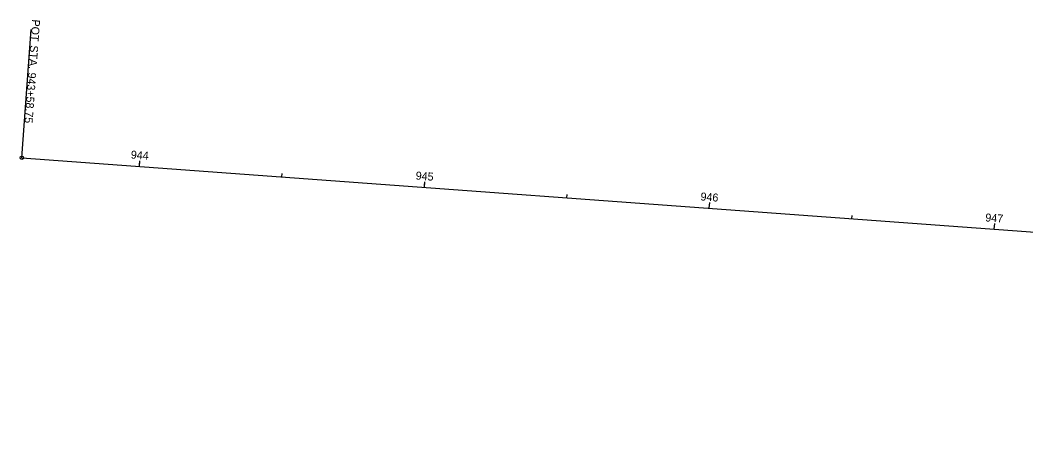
# Model space of a CAD drawing. Extents: x 1981066 to 1984208, y 708139 to 709503.
# Drawn here: x 1981065.5 to 1981417.5, y 708968.6 to 709112.1 of the extents above; entities that cross this region are included whole.
import ezdxf

# ---------------------------------------------------------------- set-up
doc = ezdxf.new("R2010")
doc.units = 0
for name, color, linetype in [('PM_X_Edge_Line', 7, 'Continuous'), ('PV_P_EOP', 7, 'Continuous'), ('PV_X_EOP', 7, 'Continuous'), ('RD_X_Wall', 7, 'Continuous'), ('SV_P_Mon_Cells_Set', 7, 'Continuous'), ('SV_X_Break_Lines', 7, 'Continuous'), ('TopoDOT Temp', 7, 'Continuous')]:
    doc.layers.add(name, color=color, linetype=linetype)

msp = doc.modelspace()

# ---------------------------------------------------------------- linework, layer by layer
at = {"layer": 'PM_X_Edge_Line'}
for p, q in [((1981107.26, 709060.84), (1981107.41, 709062.83)), ((1981157.12, 709057.17), (1981157.21, 709058.36)), ((1981206.99, 709053.5), (1981207.14, 709055.49)), ((1981256.85, 709049.83), (1981256.94, 709051.02)), ((1981306.72, 709046.16), (1981306.87, 709048.15)), ((1981356.59, 709042.49), (1981356.67, 709043.68)), ((1981406.45, 709038.82), (1981406.6, 709040.81))]:
    msp.add_line(p, q, dxfattribs=at)
at = {"layer": 'PV_P_EOP'}
msp.add_line((1981206.99, 709053.5), (1981207.08, 709054.69), dxfattribs=at)
at = {"layer": 'PV_X_EOP'}
msp.add_line((1981066.12, 709063.86), (1981069.42, 709108.74), dxfattribs=at)
msp.add_circle((1981066.12, 709063.86), 0.6, dxfattribs=at)
at = {"layer": 'RD_X_Wall'}
for p, q in [((1981107.26, 709060.84), (1981107.35, 709062.03)), ((1981206.99, 709053.5), (1981207.14, 709055.49)), ((1981306.72, 709046.16), (1981306.81, 709047.35)), ((1981406.45, 709038.82), (1981406.54, 709040.01))]:
    msp.add_line(p, q, dxfattribs=at)
at = {"layer": 'SV_P_Mon_Cells_Set'}
msp.add_line((1981066.12, 709063.86), (1981069.42, 709108.74), dxfattribs=at)
msp.add_circle((1981066.12, 709063.86), 0.6, dxfattribs=at)
at = {"layer": 'SV_X_Break_Lines'}
msp.add_line((1981066.12, 709063.86), (1982360.68, 708968.58), dxfattribs=at)
msp.add_line((1981066.12, 709063.86), (1982360.68, 708968.58), dxfattribs=at)
at = {"layer": 'TopoDOT Temp'}
msp.add_line((1981066.12, 709063.86), (1981069.42, 709108.74), dxfattribs=at)
msp.add_circle((1981066.12, 709063.86), 0.6, dxfattribs=at)

# ---------------------------------------------------------------- texts
at = {"layer": 'PM_X_Edge_Line'}
for s, p in [('944', (1981104.18, 709063.61)), ('945', (1981203.88, 709056.27)), ('946', (1981303.56, 709048.94)), ('947', (1981403.23, 709041.6))]:
    msp.add_text(s, height=2.8, rotation=355.7906, dxfattribs=at).set_placement(p)
at = {"layer": 'PV_X_EOP'}
for s, p in [('POT', (1981069.74, 709112.37)), (' STA. ', (1981069.15, 709104.35)), ('943+58.75', (1981068.37, 709093.8))]:
    msp.add_text(s, height=2.8, rotation=265.7906, dxfattribs=at).set_placement(p)
at = {"layer": 'RD_X_Wall'}
msp.add_text('945', height=2.8, rotation=355.7906, dxfattribs=at).set_placement((1981203.88, 709056.27))
at = {"layer": 'SV_P_Mon_Cells_Set'}
for s, p in [('POT', (1981069.74, 709112.37)), (' STA. ', (1981069.15, 709104.35)), ('943+58.75', (1981068.37, 709093.8))]:
    msp.add_text(s, height=2.8, rotation=265.7906, dxfattribs=at).set_placement(p)
at = {"layer": 'TopoDOT Temp'}
for s, p in [('POT', (1981069.74, 709112.37)), (' STA. ', (1981069.15, 709104.35)), ('943+58.75', (1981068.37, 709093.8))]:
    msp.add_text(s, height=2.8, rotation=265.7906, dxfattribs=at).set_placement(p)

doc.saveas('drawing.dxf')
